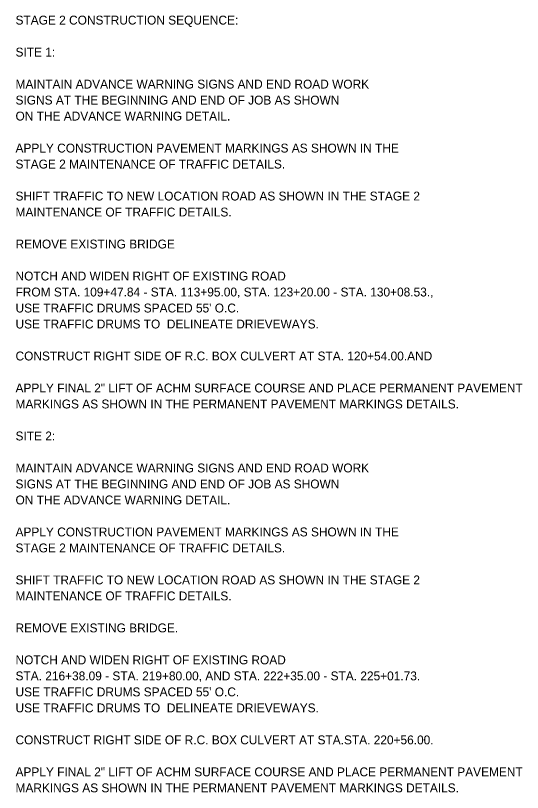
# Model space of a CAD drawing. Extents: x 1678017 to 1687792, y 404433 to 413488.
# Drawn here: x 1682431 to 1682773, y 412963 to 413488 of the extents above; entities that cross this region are included whole.
import ezdxf

# ---------------------------------------------------------------- set-up
doc = ezdxf.new("R2010")
doc.units = 0
doc.layers.add('S_MSC_PT_SYM', color=7, linetype='Continuous')

msp = doc.modelspace()

# ---------------------------------------------------------------- texts
at = {"layer": 'S_MSC_PT_SYM'}
for s, p in [('STAGE 2 CONSTRUCTION SEQUENCE:', (1682430.62, 413481.48)), ('SITE 1:', (1682430.62, 413459.88)), ('MAINTAIN ADVANCE WARNING SIGNS AND END ROAD WORK', (1682430.62, 413438.28)), ('SIGNS AT THE BEGINNING AND END OF JOB AS SHOWN', (1682430.62, 413427.48)), ('ON THE ADVANCE WARNING DETAIL.', (1682430.62, 413416.68)), ('APPLY CONSTRUCTION PAVEMENT MARKINGS AS SHOWN IN THE', (1682430.62, 413395.08)), ('STAGE 2 MAINTENANCE OF TRAFFIC DETAILS.', (1682430.62, 413384.28)), ('SHIFT TRAFFIC TO NEW LOCATION ROAD AS SHOWN IN THE STAGE 2', (1682430.62, 413362.68)), ('MAINTENANCE OF TRAFFIC DETAILS.', (1682430.62, 413351.88)), ('REMOVE EXISTING BRIDGE', (1682430.62, 413330.28)), ('NOTCH AND WIDEN RIGHT OF EXISTING ROAD ', (1682430.62, 413308.68)), ('FROM STA. 109+47.84 - STA. 113+95.00, STA. 123+20.00 - STA. 130+08.53.,', (1682430.62, 413297.88)), ("USE TRAFFIC DRUMS SPACED 55' O.C.", (1682430.62, 413287.08)), ('USE TRAFFIC DRUMS TO  DELINEATE DRIEVEWAYS.', (1682430.62, 413276.28)), ('CONSTRUCT RIGHT SIDE OF R.C. BOX CULVERT AT STA. 120+54.00.AND', (1682430.62, 413254.68)), ('APPLY FINAL 2" LIFT OF ACHM SURFACE COURSE AND PLACE PERMANENT PAVEMENT', (1682430.62, 413233.08)), ('MARKINGS AS SHOWN IN THE PERMANENT PAVEMENT MARKINGS DETAILS.', (1682430.62, 413222.28)), ('SITE 2:', (1682430.62, 413200.68)), ('MAINTAIN ADVANCE WARNING SIGNS AND END ROAD WORK', (1682430.62, 413179.08)), ('SIGNS AT THE BEGINNING AND END OF JOB AS SHOWN', (1682430.62, 413168.28)), ('ON THE ADVANCE WARNING DETAIL.', (1682430.62, 413157.48)), ('APPLY CONSTRUCTION PAVEMENT MARKINGS AS SHOWN IN THE', (1682430.62, 413135.88)), ('STAGE 2 MAINTENANCE OF TRAFFIC DETAILS.', (1682430.62, 413125.08)), ('SHIFT TRAFFIC TO NEW LOCATION ROAD AS SHOWN IN THE STAGE 2', (1682430.62, 413103.48)), ('MAINTENANCE OF TRAFFIC DETAILS.', (1682430.62, 413092.68)), ('REMOVE EXISTING BRIDGE.', (1682430.62, 413071.08)), ('NOTCH AND WIDEN RIGHT OF EXISTING ROAD ', (1682430.62, 413049.48)), ('STA. 216+38.09 - STA. 219+80.00, AND STA. 222+35.00 - STA. 225+01.73.', (1682430.62, 413038.68)), ("USE TRAFFIC DRUMS SPACED 55' O.C.", (1682430.62, 413027.88)), ('USE TRAFFIC DRUMS TO  DELINEATE DRIEVEWAYS.', (1682430.62, 413017.08)), ('CONSTRUCT RIGHT SIDE OF R.C. BOX CULVERT AT STA.STA. 220+56.00.', (1682430.62, 412995.48)), ('APPLY FINAL 2" LIFT OF ACHM SURFACE COURSE AND PLACE PERMANENT PAVEMENT', (1682430.62, 412973.88)), ('MARKINGS AS SHOWN IN THE PERMANENT PAVEMENT MARKINGS DETAILS.', (1682430.62, 412963.08))]:
    msp.add_text(s, height=6, dxfattribs=at).set_placement(p)

doc.saveas('drawing.dxf')
